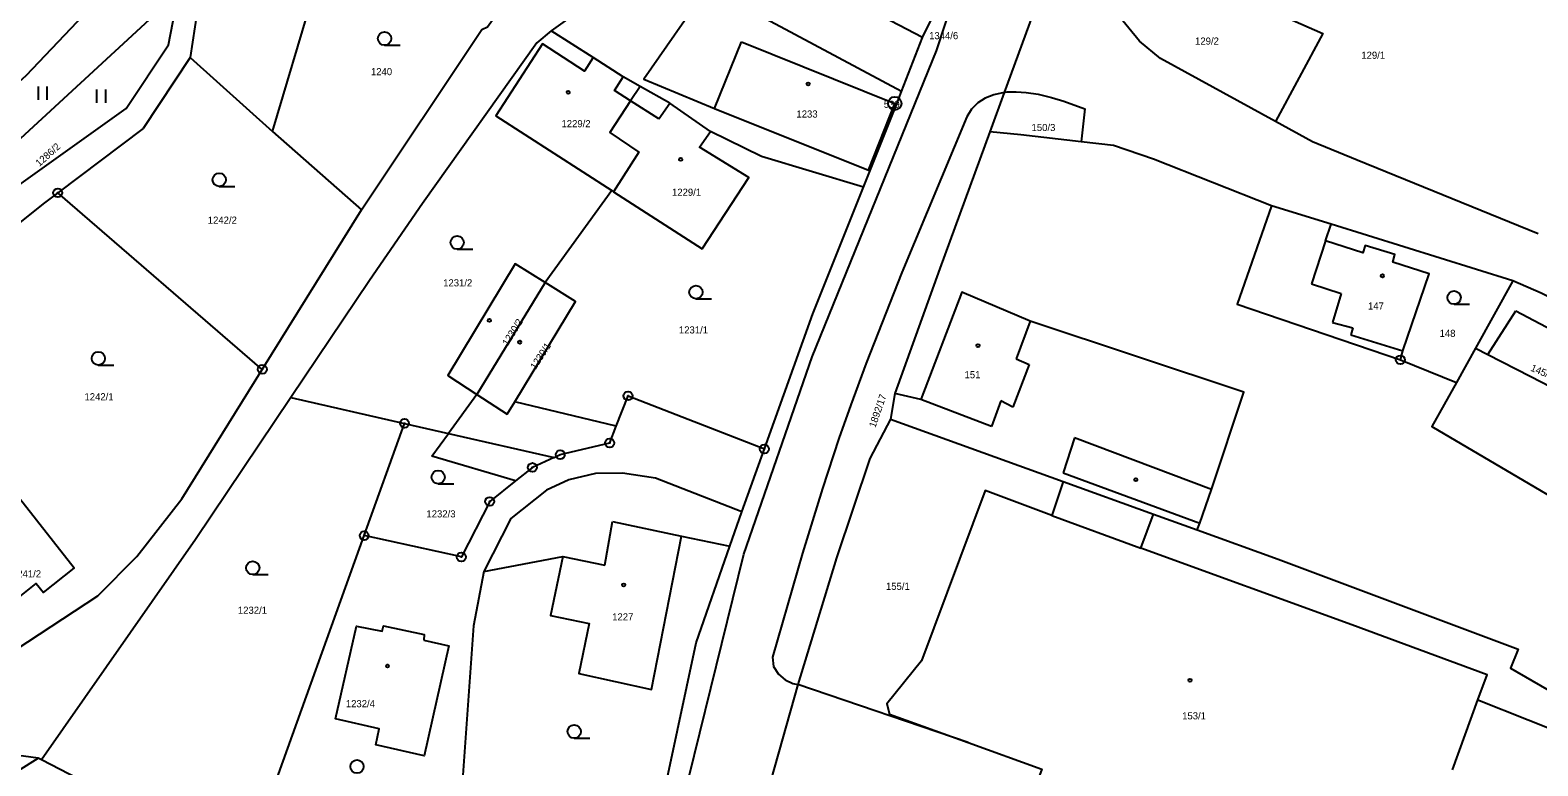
# Model space of a CAD drawing. Extents: x -587171 to -555306, y -1167727 to -1074732.
# Drawn here: x -559852.3 to -559682.1, y -1076725.4 to -1076642.4 of the extents above; entities that cross this region are included whole.
import ezdxf

# ---------------------------------------------------------------- set-up
doc = ezdxf.new("R2010")
doc.units = 0
for name, color, linetype in [('Hranice parcel', 7, 'Continuous'), ('Parcelní čísla', 7, 'Continuous'), ('Vnitřní kresba', 7, 'Continuous'), ('Značky bodu BP', 7, 'Continuous'), ('Značky budov', 7, 'Continuous'), ('Značky kultur', 7, 'Continuous')]:
    doc.layers.add(name, color=color, linetype=linetype)

msp = doc.modelspace()

# ---------------------------------------------------------------- linework, layer by layer
at = {"layer": 'Hranice parcel'}
for p, q in [((-559831.15, -1076625.18), (-559834.2, -1076645.52)), ((-559824.89, -1076653.86), (-559820.01, -1076637.34)), ((-559751.55, -1076643.25), (-559749.24, -1076638.49)), ((-559738.21, -1076638.18), (-559742.35, -1076649.45)), ((-559788.74, -1076645.51), (-559793.46, -1076642.5)), ((-559753.92, -1076649.35), (-559751.55, -1076643.25)), ((-559834.2, -1076645.52), (-559824.89, -1076653.86)), ((-559785.35, -1076647.68), (-559788.74, -1076645.51)), ((-559783.44, -1076648.76), (-559785.35, -1076647.68)), ((-559780.09, -1076650.66), (-559783.44, -1076648.76)), ((-559754.46, -1076650.74), (-559753.92, -1076649.35)), ((-559742.35, -1076649.45), (-559743.97, -1076653.88)), ((-559775.5, -1076653.86), (-559780.09, -1076650.66)), ((-559758.22, -1076660.14), (-559754.46, -1076650.74)), ((-559824.89, -1076653.86), (-559814.86, -1076662.68)), ((-559826.06, -1076680.68), (-559849.14, -1076660.77)), ((-559786.62, -1076660.52), (-559794.14, -1076670.88)), ((-559786.62, -1076660.52), (-559786.43, -1076660.64)), ((-559786.43, -1076660.64), (-559776.42, -1076667.09)), ((-559826.06, -1076680.68), (-559814.86, -1076662.68)), ((-559705.46, -1076664.31), (-559712.17, -1076662.22)), ((-559684.97, -1076670.71), (-559705.46, -1076664.31)), ((-559794.14, -1076670.88), (-559801.85, -1076683.52)), ((-559684.97, -1076670.71), (-559689.16, -1076678.29)), ((-559689.16, -1076678.29), (-559691.3, -1076682.15)), ((-559697.65, -1076679.6), (-559691.3, -1076682.15)), ((-559683.02, -1076681.45), (-559676.82, -1076684.64)), ((-559822.85, -1076683.84), (-559810.01, -1076686.77)), ((-559801.85, -1076683.52), (-559805.04, -1076687.91)), ((-559754.7, -1076683.39), (-559755.19, -1076686.3)), ((-559814.56, -1076699.43), (-559810.01, -1076686.77)), ((-559810.01, -1076686.77), (-559805.04, -1076687.91)), ((-559755.19, -1076686.3), (-559735.69, -1076693.33)), ((-559805.04, -1076687.91), (-559793.14, -1076690.62)), ((-559771.96, -1076696.75), (-559769.41, -1076689.66)), ((-559735.69, -1076693.33), (-559725.52, -1076697)), ((-559773.32, -1076700.63), (-559771.96, -1076696.75)), ((-559725.52, -1076697), (-559720.56, -1076698.79)), ((-559828.11, -1076737.08), (-559814.56, -1076699.43)), ((-559765.64, -1076716.22), (-559768.67, -1076727.01)), ((-559746.4, -1076722.75), (-559765.64, -1076716.22)), ((-559691.78, -1076725.84), (-559688.89, -1076717.96)), ((-559861.1, -1076730.63), (-559851.34, -1076724.55)), ((-559850.96, -1076724.72), (-559851.34, -1076724.55))]:
    msp.add_line(p, q, dxfattribs=at)
for points in [[(-559886.72, -1076702.24), (-559876.58, -1076686.53), (-559863.65, -1076668.94), (-559859.88, -1076664.4), (-559841.42, -1076651.26), (-559836.65, -1076644.06), (-559833.46, -1076627.56), (-559832.51, -1076620.32), (-559830.89, -1076610.06), (-559828.66, -1076600.86)], [(-559890.81, -1076700.51), (-559867.4, -1076667.56), (-559838.3, -1076640.75), (-559833.93, -1076609.06)], [(-559854.21, -1076648.87), (-559852.71, -1076647.52), (-559843.31, -1076637.61), (-559837.97, -1076609.15)], [(-559734.92, -1076630.24), (-559706.39, -1076642.78), (-559711.75, -1076652.73)], [(-559814.86, -1076662.68), (-559801.29, -1076642.33), (-559800.66, -1076642.03), (-559798.13, -1076638.47), (-559796.02, -1076639.07), (-559795.27, -1076637.84), (-559788.87, -1076633.47)], [(-559771.51, -1076634.29), (-559777.37, -1076634.48), (-559780.58, -1076635.26), (-559785.5, -1076637.28), (-559788.82, -1076639.17), (-559793.46, -1076642.5)], [(-559751.55, -1076643.25), (-559759.59, -1076639.07), (-559767.4, -1076635.58), (-559771.51, -1076634.29)], [(-559753.92, -1076649.35), (-559775.82, -1076637.62), (-559783, -1076647.94), (-559775.02, -1076651.27), (-559757.65, -1076658.22), (-559754.7, -1076650.68), (-559754.46, -1076650.74)], [(-559711.75, -1076652.73), (-559724.7, -1076645.61), (-559727.09, -1076643.65), (-559731.04, -1076638.8)], [(-559793.46, -1076642.5), (-559795.07, -1076643.86), (-559807.97, -1076661.96), (-559813.98, -1076670.66), (-559822.85, -1076683.84)], [(-559788.74, -1076645.51), (-559789.72, -1076647.05), (-559794.43, -1076643.98), (-559799.7, -1076652.1), (-559786.62, -1076660.52)], [(-559834.2, -1076645.52), (-559839.51, -1076653.51), (-559849.14, -1076660.77)], [(-559783.44, -1076648.76), (-559784.5, -1076650.38), (-559786.84, -1076653.97), (-559783.56, -1076656.19), (-559786.43, -1076660.64)], [(-559742.35, -1076649.45), (-559743.52, -1076649.7), (-559744.48, -1076650.1), (-559745.33, -1076650.62), (-559746.05, -1076651.33), (-559746.58, -1076652.19), (-559753.89, -1076669.77), (-559757.93, -1076679.98), (-559759.67, -1076684.67), (-559761.02, -1076688.48), (-559762.86, -1076694.1), (-559765.12, -1076701.43), (-559768.48, -1076713.15), (-559768.36, -1076714.19), (-559767.82, -1076715.05), (-559767.07, -1076715.71), (-559766.21, -1076716.1), (-559765.64, -1076716.22)], [(-559742.35, -1076649.45), (-559742.02, -1076649.39), (-559740.99, -1076649.38), (-559739.88, -1076649.45), (-559738.51, -1076649.63), (-559737.02, -1076650.01), (-559735.61, -1076650.43), (-559733.24, -1076651.28), (-559733.67, -1076655.02)], [(-559682.11, -1076665.41), (-559702.52, -1076657.09), (-559707.56, -1076655.03), (-559711.75, -1076652.73)], [(-559776.42, -1076667.09), (-559771.15, -1076659.05), (-559776.73, -1076655.61), (-559775.5, -1076653.86)], [(-559758.22, -1076660.14), (-559769.73, -1076656.68), (-559775.5, -1076653.86)], [(-559743.97, -1076653.88), (-559749.61, -1076669.3), (-559754.7, -1076683.39)], [(-559733.67, -1076655.02), (-559740.46, -1076654.24), (-559743.97, -1076653.88)], [(-559712.17, -1076662.22), (-559725.52, -1076656.96), (-559730.02, -1076655.44), (-559733.67, -1076655.02)], [(-559849.14, -1076660.77), (-559850.79, -1076662.01), (-559864.54, -1076673.01)], [(-559769.41, -1076689.66), (-559763.93, -1076674.42), (-559758.22, -1076660.14)], [(-559712.17, -1076662.22), (-559716.07, -1076673.31), (-559697.65, -1076679.6)], [(-559697.65, -1076679.6), (-559697.37, -1076678.59), (-559694.4, -1076669.89), (-559698.5, -1076668.59), (-559698.27, -1076667.71), (-559701.61, -1076666.7), (-559701.9, -1076667.52), (-559706.09, -1076666.2), (-559705.46, -1076664.31)], [(-559794.14, -1076670.88), (-559797.52, -1076668.77), (-559805.12, -1076681.39), (-559801.85, -1076683.52)], [(-559786.13, -1076687.1), (-559797.58, -1076684.34), (-559790.7, -1076673.03), (-559794.14, -1076670.88)], [(-559720.56, -1076698.79), (-559720.29, -1076698.02), (-559718.96, -1076694.24), (-559715.32, -1076683.25), (-559739.4, -1076675.26), (-559747.12, -1076671.98), (-559751.77, -1076684.08), (-559754.7, -1076683.39)], [(-559667.45, -1076680.63), (-559676.49, -1076674.75), (-559681.77, -1076672.1), (-559684.97, -1076670.71)], [(-559857.82, -1076709.81), (-559851.57, -1076704.83), (-559850.74, -1076705.83), (-559847.3, -1076703.1), (-559853.88, -1076694.72), (-559864.54, -1076673.01)], [(-559689.16, -1076678.29), (-559687.79, -1076678.99), (-559683.02, -1076681.45)], [(-559855.15, -1076713.16), (-559844.62, -1076706.22), (-559840.22, -1076701.79), (-559835.14, -1076695.29), (-559826.06, -1076680.68)], [(-559691.3, -1076682.15), (-559694.11, -1076687.14), (-559668.8, -1076702)], [(-559822.85, -1076683.84), (-559833.6, -1076699.88), (-559850.96, -1076724.72)], [(-559786.13, -1076687.1), (-559784.79, -1076683.67), (-559769.41, -1076689.66)], [(-559793.14, -1076690.62), (-559792.44, -1076690.3), (-559786.86, -1076688.98), (-559786.13, -1076687.1)], [(-559755.19, -1076686.3), (-559757.52, -1076690.73), (-559761.28, -1076701.94), (-559765.64, -1076716.22)], [(-559793.14, -1076690.62), (-559795.58, -1076691.74), (-559797.5, -1076693.27), (-559800.4, -1076695.58), (-559803.6, -1076701.84), (-559814.56, -1076699.43)], [(-559771.96, -1076696.75), (-559781.69, -1076692.96), (-559785.42, -1076692.38), (-559788.45, -1076692.44), (-559791.46, -1076693.15), (-559794, -1076694.31), (-559798.02, -1076697.52), (-559801.07, -1076703.48)], [(-559735.69, -1076693.33), (-559736.98, -1076697.18), (-559744.51, -1076694.35), (-559751.69, -1076713.55), (-559755.6, -1076718.39), (-559755.28, -1076719.57), (-559746.4, -1076722.75)], [(-559688.89, -1076717.96), (-559687.86, -1076715.15), (-559703.12, -1076709.51), (-559726.93, -1076700.84), (-559725.52, -1076697)], [(-559720.56, -1076698.79), (-559711.44, -1076702.08), (-559684.36, -1076712.24), (-559685.23, -1076714.39), (-559666.86, -1076725), (-559642.31, -1076739.18), (-559645.66, -1076744.62), (-559629.37, -1076754.08), (-559588.91, -1076777.58)], [(-559801.07, -1076703.48), (-559792.14, -1076701.78), (-559793.53, -1076708.44), (-559789.17, -1076709.35), (-559790.34, -1076714.98), (-559782.13, -1076716.78), (-559778.76, -1076699.49), (-559773.32, -1076700.63)], [(-559786.45, -1076755.33), (-559777.11, -1076711.53), (-559773.32, -1076700.63)], [(-559801.07, -1076703.48), (-559802.23, -1076709.62), (-559803.57, -1076728.54), (-559804.06, -1076731.73)], [(-559807.84, -1076711.22), (-559805.02, -1076711.86), (-559807.8, -1076724.28), (-559813.25, -1076723.02), (-559812.88, -1076721.21), (-559817.8, -1076720.1), (-559815.42, -1076709.63), (-559812.54, -1076710.22), (-559812.4, -1076709.61), (-559807.79, -1076710.6), (-559807.84, -1076711.22)], [(-559688.89, -1076717.96), (-559671.86, -1076724.73), (-559673.26, -1076728.55), (-559668.97, -1076730.19), (-559667.59, -1076730.71), (-559648.53, -1076737.98), (-559651.16, -1076745.12), (-559619.72, -1076763.12), (-559593.71, -1076778), (-559592.61, -1076778.63), (-559604.86, -1076800), (-559615.04, -1076794.19), (-559659.82, -1076768.6), (-559665.81, -1076765.18), (-559663.2, -1076758.81), (-559677.44, -1076753.47)], [(-559746.4, -1076722.75), (-559738.1, -1076725.77), (-559738.48, -1076726.8), (-559737.15, -1076727.29), (-559732.38, -1076729.02), (-559733.58, -1076732.32), (-559704.76, -1076743.24), (-559701.62, -1076744.18)], [(-559851.34, -1076724.55), (-559859.71, -1076723.41), (-559881.31, -1076738.34), (-559883.05, -1076744.29)], [(-559835.03, -1076733.2), (-559845.8, -1076727.41), (-559850.96, -1076724.72)]]:
    msp.add_lwpolyline(points, dxfattribs=at)
at = {"layer": 'Vnitřní kresba'}
for p, q in [((-559750, -1076644.76), (-559747.53, -1076637.29)), ((-559775.02, -1076651.27), (-559771.97, -1076643.74)), ((-559771.97, -1076643.74), (-559754.7, -1076650.68)), ((-559764.03, -1076679.27), (-559750, -1076644.76)), ((-559781.31, -1076652.42), (-559784.5, -1076650.38)), ((-559781.31, -1076652.42), (-559780.09, -1076650.66)), ((-559706.09, -1076666.2), (-559707.66, -1076671.05)), ((-559707.66, -1076671.05), (-559704.31, -1076672.12)), ((-559704.31, -1076672.12), (-559705.31, -1076675.38)), ((-559739.4, -1076675.26), (-559741, -1076679.51)), ((-559705.31, -1076675.38), (-559703, -1076675.99)), ((-559687.79, -1076678.99), (-559684.61, -1076674.09)), ((-559684.61, -1076674.09), (-559679.84, -1076676.6)), ((-559703, -1076675.99), (-559703.24, -1076676.79)), ((-559703.24, -1076676.79), (-559697.37, -1076678.59)), ((-559771.72, -1076701.51), (-559764.03, -1076679.27)), ((-559739.53, -1076680.14), (-559741.39, -1076684.93)), ((-559741, -1076679.51), (-559739.53, -1076680.14)), ((-559801.85, -1076683.52), (-559798.44, -1076685.74)), ((-559798.44, -1076685.74), (-559797.58, -1076684.34)), ((-559743.78, -1076687.14), (-559751.77, -1076684.08)), ((-559742.73, -1076684.24), (-559743.78, -1076687.14)), ((-559741.39, -1076684.93), (-559742.73, -1076684.24)), ((-559806.91, -1076690.48), (-559805.04, -1076687.91)), ((-559734.42, -1076688.42), (-559735.69, -1076692.34)), ((-559718.96, -1076694.24), (-559734.42, -1076688.42)), ((-559797.5, -1076693.27), (-559806.91, -1076690.48)), ((-559735.69, -1076692.34), (-559720.29, -1076698.02)), ((-559736.98, -1076697.18), (-559726.93, -1076700.84)), ((-559787.42, -1076702.77), (-559786.53, -1076697.83)), ((-559786.53, -1076697.83), (-559778.76, -1076699.49)), ((-559792.14, -1076701.78), (-559787.42, -1076702.77)), ((-559777.92, -1076726.7), (-559771.72, -1076701.51))]:
    msp.add_line(p, q, dxfattribs=at)
msp.add_lwpolyline([(-559784.5, -1076650.38), (-559786.33, -1076649.21), (-559785.35, -1076647.68)], dxfattribs=at)
at = {"layer": 'Značky bodu BP'}
for centre, radius in [((-559754.7, -1076650.68), 0.75), ((-559754.7, -1076650.68), 0.03), ((-559849.14, -1076660.77), 0.5), ((-559849.14, -1076660.77), 0.0303), ((-559826.06, -1076680.68), 0.5), ((-559697.65, -1076679.6), 0.5), ((-559697.65, -1076679.6), 0.0303), ((-559826.06, -1076680.68), 0.0303), ((-559784.79, -1076683.67), 0.5), ((-559784.79, -1076683.67), 0.0303), ((-559810.01, -1076686.77), 0.5), ((-559810.01, -1076686.77), 0.0303), ((-559786.86, -1076688.98), 0.5), ((-559786.86, -1076688.98), 0.0303), ((-559792.44, -1076690.3), 0.5), ((-559792.44, -1076690.3), 0.0303), ((-559769.41, -1076689.66), 0.5), ((-559769.41, -1076689.66), 0.0303), ((-559795.58, -1076691.74), 0.5), ((-559795.58, -1076691.74), 0.0303), ((-559800.4, -1076695.58), 0.5), ((-559800.4, -1076695.58), 0.0303), ((-559814.56, -1076699.43), 0.5), ((-559814.56, -1076699.43), 0.0303), ((-559803.6, -1076701.84), 0.5), ((-559803.6, -1076701.84), 0.0303)]:
    msp.add_circle(centre, radius, dxfattribs=at)
at = {"layer": 'Značky budov'}
for centre in [(-559791.54, -1076649.43), (-559764.47, -1076648.5), (-559778.85, -1076657), (-559699.68, -1076670.13), (-559800.43, -1076675.15), (-559797.01, -1076677.61), (-559745.31, -1076678), (-559727.49, -1076693.12), (-559785.28, -1076705), (-559811.93, -1076714.15), (-559721.39, -1076715.75)]:
    msp.add_circle(centre, 0.175, dxfattribs=at)
at = {"layer": 'Značky kultur'}
for p, q in [((-559812.26, -1076644.12), (-559810.51, -1076644.12)), ((-559851.32, -1076650.26), (-559851.32, -1076648.76)), ((-559850.32, -1076650.26), (-559850.32, -1076648.76)), ((-559844.71, -1076650.6), (-559844.71, -1076649.1)), ((-559843.71, -1076650.6), (-559843.71, -1076649.1)), ((-559830.91, -1076660.04), (-559829.16, -1076660.04)), ((-559804.07, -1076667.13), (-559802.32, -1076667.13)), ((-559777.13, -1076672.72), (-559775.38, -1076672.72)), ((-559691.59, -1076673.34), (-559689.84, -1076673.34)), ((-559844.56, -1076680.2), (-559842.81, -1076680.2)), ((-559806.21, -1076693.58), (-559804.46, -1076693.58)), ((-559827.14, -1076703.83), (-559825.39, -1076703.83)), ((-559790.86, -1076722.29), (-559789.11, -1076722.29))]:
    msp.add_line(p, q, dxfattribs=at)
for centre in [(-559812.26, -1076643.37), (-559830.91, -1076659.29), (-559804.07, -1076666.38), (-559777.13, -1076671.97), (-559691.59, -1076672.59), (-559844.56, -1076679.45), (-559806.21, -1076692.83), (-559827.14, -1076703.08), (-559790.86, -1076721.54), (-559815.37, -1076725.48)]:
    msp.add_circle(centre, 0.75, dxfattribs=at)

# ---------------------------------------------------------------- texts
at = {"layer": 'Parcelní čísla'}
for s, p in [('1344/6', (-559750.82, -1076643.44)), ('129/2', (-559720.81, -1076644.05)), ('129/1', (-559702.05, -1076645.65)), ('1240', (-559813.8, -1076647.5)), ('1233', (-559765.79, -1076652.28)), ('1229/2', (-559792.3, -1076653.37)), ('150/3', (-559739.26, -1076653.8)), ('1229/1', (-559779.83, -1076661.1)), ('1242/2', (-559832.21, -1076664.25)), ('1231/2', (-559805.65, -1076671.32)), ('147', (-559701.3, -1076673.93)), ('1231/1', (-559779.05, -1076676.63)), ('148', (-559693.22, -1076677.02)), ('151', (-559746.82, -1076681.68)), ('1242/1', (-559846.12, -1076684.17)), ('1232/3', (-559807.54, -1076697.38)), ('1241/2', (-559854.3, -1076704.14)), ('155/1', (-559755.69, -1076705.55)), ('1232/1', (-559828.81, -1076708.25)), ('1227', (-559786.58, -1076709)), ('1232/4', (-559816.63, -1076718.79)), ('153/1', (-559722.27, -1076720.16))]:
    msp.add_text(s, height=0.803, dxfattribs=at).set_placement(p)
for s, rotation, p in [('1286/2', 42, (-559851.21, -1076657.86)), ('1230/2', 58, (-559798.36, -1076678.09)), ('1230/1', 57, (-559795.22, -1076680.76)), ('145/1', 337, (-559683.03, -1076680.81)), ('1892/17', 71, (-559756.88, -1076687.32))]:
    msp.add_text(s, height=0.803, rotation=rotation, dxfattribs=at).set_placement(p)
at = {"layer": 'Značky bodu BP'}
msp.add_text('539', height=0.803, dxfattribs=at).set_placement((-559755.93, -1076651.18))

doc.saveas('drawing.dxf')
